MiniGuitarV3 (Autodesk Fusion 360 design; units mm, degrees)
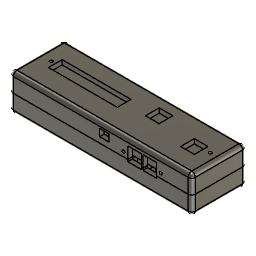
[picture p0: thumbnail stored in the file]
part number: 2026-04-03-11-49-24-486
part number: 2026-04-03-20-17-09-000
part number: 2026-04-03-20-17-09-014
part number: 2026-04-03-20-17-09-018
part number: 2026-04-03-20-17-09-022
part number: 2026-04-03-20-17-09-025
sketch "Sketch1" plane through (0, 0, 0) normal (0, 0, 1) x axis (1, 0, 0)
sketch "Sketch5" plane through (0, 0, 0) normal (0, 0, 1) x axis (1, 0, 0)
  line L1 (101.6, 0) -> (-152.4, 0)
  line L2 (101.6, -76.2) -> (101.6, 0)
  line L3 (-152.4, -76.2) -> (101.6, -76.2)
  line L4 (-152.4, 0) -> (-152.4, -76.2)
  horizontal L1
  perpendicular L1 L2
  perpendicular L2 L3
  perpendicular L1 L4
extrude "Extrude2" new body sketch "Sketch5" along normal blind 50.8
sketch "Sketch6" plane through (0, -76.2, 0) normal (0, -1, 0) x axis (1, 0, 0)
  line L1 (101.6, 0) -> (-152.4, 0)
  line L2 (101.6, 50.8) -> (101.6, 0)
  line L3 (-152.4, 50.8) -> (101.6, 50.8)
  line L4 (-152.4, 0) -> (-152.4, 50.8)
  line L5 (63.5, 25.4) -> (-127, 25.4)
  horizontal L5
split "Split2"
move "Move2"
shell "Shell3" innerThickness 6.35
shell "Shell4" innerThickness 6.35
sketch "Sketch7" plane through (0, 0, 73.66) normal (0, 0, 1) x axis (-1, 0, 0)
  line L1 (-101.6, 76.2) -> (152.4, 76.2)
  line L2 (-101.6, 0) -> (-101.6, 76.2)
  line L3 (152.4, 0) -> (-101.6, 0)
  line L4 (152.4, 76.2) -> (152.4, 0)
fillet "Fillet2" radius 5.08
fillet "Fillet3" radius 5.08
sketch "Sketch8" plane through (0, 0, 73.66) normal (0, 0, 1) x axis (-1, 0, 0)
sketch "Sketch9" plane through (0, 0, 73.66) normal (0, 0, 1) x axis (-1, 0, 0)
  line L1 (33.02, 25.4) -> (139.7, 25.4)
  line L2 (33.02, 15.9736) -> (33.02, 25.4)
  line L3 (-93.98, 15.9736) -> (33.02, 15.9736)
  line L4 (-93.98, 51.2796) -> (-93.98, 15.9736)
  line L5 (-53.34, 51.2796) -> (-93.98, 51.2796)
  line L6 (-53.34, 60.1632) -> (-53.34, 51.2796)
  line L7 (10.16, 60.1632) -> (-53.34, 60.1632)
  line L8 (10.16, 47.4632) -> (10.16, 60.1632)
  line L9 (139.7, 47.4632) -> (10.16, 47.4632)
  line L10 (139.7, 25.4) -> (139.7, 47.4632)
  point P5 (-93.98, 15.9736)
  point P6 (-93.98, 51.2796)
  point P9 (10.16, 60.1632)
  point P10 (10.16, 47.4632)
  horizontal L1
  perpendicular L1 L2
  perpendicular L2 L3
  perpendicular L3 L4
  perpendicular L4 L5
  perpendicular L5 L6
  perpendicular L6 L7
  perpendicular L7 L8
  perpendicular L8 L9
  perpendicular L1 L10
  dimension "d16" distance P5 P6 = 35.306
  dimension "d17" distance P9 P10 = 12.7
sketch "Sketch10" plane through (0, 0, 73.66) normal (0, 0, 1) x axis (-1, 0, 0)
  line L1 (134.2136, 35.56) -> (139.7, 35.56)
  point P2 (139.7, 35.56)
  point P3 (134.2136, 35.56)
  horizontal L1
  dimension "d18" distance P2 P3 = 5.4864
sketch "Sketch11" plane through (0, 0, 73.66) normal (0, 0, 1) x axis (-1, 0, 0)
  line L1 (139.8217, 36.3604) -> (139.8217, 25.3604)
  line L2 (134.3217, 36.3604) -> (139.8217, 36.3604)
  point P2 (139.8217, 25.3604)
  point P3 (139.8217, 36.3604)
  point P4 (134.3217, 36.3604)
  vertical L1
  perpendicular L1 L2
  dimension "d22" distance P2 P3 = 11
  dimension "d23" distance P3 P4 = 5.5
hole "Hole2" HoleDepth 13 HoleDiameter 4.1 TipAngle 118
sketch "Sketch12" plane through (0, 0, 73.66) normal (0, 0, 1) x axis (-1, 0, 0)
sketch "Sketch13" plane through (0, 0, 73.66) normal (0, 0, 1) x axis (-1, 0, 0)
  line L1 (-94, 36) -> (-94, 51)
  line L2 (-87.5, 36) -> (-94, 36)
  point P3 (-94, 36)
  point P4 (-87.5, 36)
  vertical L1
  perpendicular L1 L2
  dimension "d27" distance P3 P4 = 6.5
hole "Hole3" HoleDepth 13 HoleDiameter 4.1 TipAngle 118
sketch "Sketch14" plane through (0, 0, 73.66) normal (0, 0, 1) x axis (-1, 0, 0)
sketch "Sketch19" plane through (0, 0, 73.66) normal (0, 0, 1) x axis (-1, 0, 0)
  line L1 (51.5602, 45.9984) -> (42.0402, 45.9984)
  line L2 (51.5602, 26.9484) -> (51.5602, 45.9984)
  line L3 (32.5102, 26.9484) -> (51.5602, 26.9484)
  line L4 (32.5102, 45.9984) -> (32.5102, 26.9484)
  line L5 (42.0402, 45.9984) -> (32.5102, 45.9984)
  line L6 (51.7702, 46.0184) -> (61.2902, 46.0184)
  line L7 (51.7702, 27) -> (51.7702, 46.0184)
  line L8 (70.8202, 27) -> (51.7702, 27)
  line L9 (70.8202, 46.0184) -> (70.8202, 27)
  line L10 (61.2902, 46.0184) -> (70.8202, 46.0184)
  line L11 (71.0202, 46.0184) -> (80.5402, 46.0184)
  line L12 (71.0202, 27) -> (71.0202, 46.0184)
  line L13 (90.0702, 27) -> (71.0202, 27)
  line L14 (90.0702, 46.0184) -> (90.0702, 27)
  line L15 (80.5402, 46.0184) -> (90.0702, 46.0184)
  line L16 (90.2702, 46.0184) -> (99.7902, 46.0184)
  line L17 (90.2702, 26.9684) -> (90.2702, 46.0184)
  line L18 (109.3202, 26.9684) -> (90.2702, 26.9684)
  line L19 (109.4152, 46.0184) -> (109.3202, 26.9684)
  line L20 (99.7902, 46.0184) -> (109.4152, 46.0184)
  line L21 (109.5202, 46.0184) -> (119.0402, 46)
  line L22 (109.5202, 26.9684) -> (109.5202, 46.0184)
  line L23 (128.5702, 26.9684) -> (109.5202, 26.9684)
  line L24 (128.5702, 46.0184) -> (128.5702, 26.9684)
  line L25 (119.0402, 46) -> (128.5702, 46.0184)
  point P13 (71.0202, 46.0184)
  point P18 (90.2702, 46.0184)
  point P23 (109.5202, 46.0184)
  point P2 (42.0402, 45.9984)
  point P3 (51.5602, 45.9984)
  point P4 (51.5602, 26.9484)
  point P5 (32.5102, 26.9484)
  point P7 (61.2902, 46.0184)
  point P8 (51.7702, 46.0184)
  point P9 (51.7702, 27)
  point P10 (70.8202, 27)
  point P12 (80.5402, 46.0184)
  point P14 (71.0202, 27)
  point P15 (90.0702, 27)
  point P17 (99.7902, 46.0184)
  point P19 (90.2702, 26.9684)
  point P20 (109.3202, 26.9684)
  point P22 (119.0402, 46)
  point P24 (109.5202, 26.9684)
  point P25 (128.5702, 26.9684)
  perpendicular L1 L2
  perpendicular L2 L3
  perpendicular L3 L4
  perpendicular L2 L6
  perpendicular L6 L7
  perpendicular L7 L8
  perpendicular L6 L9
  coincident L10 P13
  perpendicular L9 L11
  perpendicular L10 L12
  perpendicular L9 L13
  perpendicular L13 L14
  coincident L15 P18
  perpendicular L14 L16
  perpendicular L13 L17
  perpendicular L17 L18
  coincident L20 P23
  perpendicular L18 L22
  perpendicular L22 L23
  perpendicular L18 L24
  dimension "d47" distance P2 P3 = 9.52
  dimension "d48" distance P3 P4 = 19.05
  dimension "d49" distance P4 P5 = 19.05
  dimension "d52" distance P7 P8 = 9.52
  dimension "d53" distance P9 P10 = 19.05
  dimension "d55" distance P12 P13 = 9.52
  dimension "d56" distance P14 P15 = 19.05
  dimension "d58" distance P17 P18 = 9.52
  dimension "d59" distance P18 P19 = 19.05
  dimension "d60" distance P19 P20 = 19.05
  dimension "d61" distance P22 P23 = 9.52
  dimension "d62" distance P24 P25 = 19.05
extrude "Extrude4" cut sketch "Sketch19" profile of L21 L22 L23 L24 L25 against normal blind 15
extrude "Extrude5" cut sketch "Sketch19" profile of L16 L17 L18 L19 L20 against normal blind 8
extrude "Extrude6" cut sketch "Sketch19" profile of L11 L12 L13 L14 L15 against normal blind 12
extrude "Extrude7" cut sketch "Sketch19" profile of L6 L7 L8 L9 L10 against normal blind 10
extrude "Extrude8" cut sketch "Sketch19" profile of L1 L2 L3 L4 L5 against normal blind 7
sketch "Sketch20" plane through (0, 0, 73.66) normal (0, 0, 1) x axis (-1, 0, 0)
  line L1 (128.5789, 46) -> (128.5789, 26.9688)
  line L2 (32.5156, 46) -> (128.5789, 46)
  line L3 (32.5046, 26.9365) -> (32.5156, 46)
  line L4 (128.5789, 26.8811) -> (32.5046, 26.9365)
  line L5 (128.5789, 27.2773) -> (128.5789, 26.8811)
  point P7 (128.5789, 27.2773)
  vertical L1
  perpendicular L1 L2
  perpendicular L3 L4
  coincident L1 P7
  parallel L1 L5
extrude "Extrude9" cut sketch "Sketch20" against normal blind 8
sketch "Sketch21" plane through (0, 0, 73.66) normal (0, 0, 1) x axis (-1, 0, 0)
sketch "Sketch22" plane through (0, 0, 73.66) normal (0, 0, 1) x axis (-1, 0, 0)
  line L1 (2.52, 17.48) -> (2.52, 27)
  line L2 (-16.53, 17.48) -> (2.52, 17.48)
  line L3 (-16.53, 36.53) -> (-16.53, 17.48)
  line L4 (2.52, 36.53) -> (-16.53, 36.53)
  line L5 (2.52, 27) -> (2.52, 36.53)
  point P2 (2.52, 27)
  point P3 (2.52, 17.48)
  point P4 (-16.53, 17.48)
  point P5 (-16.53, 36.53)
  perpendicular L1 L2
  perpendicular L2 L3
  perpendicular L3 L4
  dimension "d83" distance P2 P3 = 9.52
  dimension "d84" distance P3 P4 = 19.05
  dimension "d85" distance P4 P5 = 19.05
extrude "Extrude10" cut sketch "Sketch22" against normal blind 11
sketch "Sketch23" plane through (0, 0, 73.66) normal (0, 0, 1) x axis (-1, 0, 0)
  line L1 (-59.1985, 49.1388) -> (-59.1985, 39.6188)
  line L2 (-78.2485, 49.1388) -> (-59.1985, 49.1388)
  line L3 (-78.2485, 30.0888) -> (-78.2485, 49.1388)
  line L4 (-59.1985, 30.0888) -> (-78.2485, 30.0888)
  line L5 (-59.1985, 39.6188) -> (-59.1985, 30.0888)
  point P2 (-59.1985, 39.6188)
  point P3 (-59.1985, 49.1388)
  point P4 (-78.2485, 49.1388)
  point P5 (-78.2485, 30.0888)
  point P6 (-59.1985, 30.0888)
  perpendicular L1 L2
  perpendicular L3 L4
  dimension "d90" distance P2 P3 = 9.52
  dimension "d91" distance P3 P4 = 19.05
  dimension "d92" distance P4 P5 = 19.05
  dimension "d93" distance P5 P6 = 19.05
extrude "Extrude11" cut sketch "Sketch23" against normal blind 12
sketch "Sketch24" plane through (0, -76.2, 0) normal (0, -1, 0) x axis (1, 0, 0)
  line L1 (-147.32, 48.26) -> (-147.32, 68.58)
  line L2 (96.52, 48.26) -> (-147.32, 48.26)
  line L3 (96.52, 68.58) -> (96.52, 48.26)
  line L4 (-147.32, 68.58) -> (96.52, 68.58)
move "Move3"
fillet "Fillet4" radius 5
move "Move4"
move "Move5"
sketch "Sketch25" plane through (0, -76.2, 0) normal (0, -1, 0) x axis (1, 0, 0)
sketch "Sketch26" plane through (0, -76.2, 0) normal (0, -1, 0) x axis (1, 0, 0)
sketch "Sketch27" plane through (0, -76.2, 0) normal (0, -1, 0) x axis (1, 0, 0)
sketch "Sketch28" plane through (0, -76.2, 0) normal (0, -1, 0) x axis (1, 0, 0)
  line L1 (1, 44) -> (1, 65)
  vertical L1
sketch "Sketch29" plane through (0, -76.2, 0) normal (0, -1, 0) x axis (1, 0, 0)
  line L1 (65, 54.5) -> (65, 65)
  line L2 (58.5, 54.5) -> (65, 54.5)
  point P2 (65, 65)
  point P3 (65, 54.5)
  point P4 (58.5, 54.5)
  vertical L1
  perpendicular L1 L2
  dimension "d99" distance P2 P3 = 10.5
  dimension "d100" distance P3 P4 = 6.5
hole "Hole4" HoleDepth 13 HoleDiameter 4.1 TipAngle 118
sketch "Sketch30" plane through (0, -76.2, 0) normal (0, -1, 0) x axis (1, 0, 0)
  line L1 (1, 54.5) -> (1, 65)
  line L2 (6.5, 54.5) -> (1, 54.5)
  point P2 (1, 65)
  point P3 (1, 54.5)
  point P4 (6.5, 54.5)
  vertical L1
  perpendicular L1 L2
  dimension "d104" distance P2 P3 = 10.5
  dimension "d105" distance P3 P4 = 5.5
hole "Hole5" HoleDepth 13 HoleDiameter 4.1 TipAngle 118
sketch "Sketch31" plane through (0, -76.2, 0) normal (0, -1, 0) x axis (1, 0, 0)
sketch "Sketch32" plane through (0, -76.2, 0) normal (0, -1, 0) x axis (1, 0, 0)
  line L1 (33.48, 45.48) -> (43, 45.48)
  line L2 (33.48, 64.53) -> (33.48, 45.48)
  line L3 (52.53, 64.53) -> (33.48, 64.53)
  line L4 (52.53, 45.48) -> (52.53, 64.53)
  line L5 (43, 45.48) -> (52.53, 45.48)
  point P2 (43, 45.48)
  point P3 (33.48, 45.48)
  point P4 (33.48, 64.53)
  point P5 (52.53, 64.53)
  perpendicular L1 L2
  perpendicular L3 L4
  dimension "d111" distance P2 P3 = 9.52
  dimension "d112" distance P3 P4 = 19.05
  dimension "d113" distance P4 P5 = 19.05
sketch "Sketch33" plane through (0, -76.2, 0) normal (0, -1, 0) x axis (1, 0, 0)
  line L1 (12.48, 64.52) -> (22, 64.52)
  line L2 (12.48, 45.47) -> (12.48, 64.52)
  line L3 (31.53, 45.47) -> (12.48, 45.47)
  line L4 (31.53, 64.52) -> (31.53, 45.47)
  line L5 (22, 64.52) -> (31.53, 64.52)
  point P2 (22, 64.52)
  point P3 (12.48, 64.52)
  point P4 (12.48, 45.47)
  point P5 (31.53, 45.47)
  perpendicular L2 L3
  dimension "d116" distance P2 P3 = 9.52
  dimension "d117" distance P3 P4 = 19.05
  dimension "d118" distance P4 P5 = 19.05
extrude "Extrude12" cut sketch "Sketch33" against normal blind 17
extrude "Extrude13" cut sketch "Sketch32" against normal blind 24
sketch "Sketch34" plane through (0, -76.2, 0) normal (0, -1, 0) x axis (1, 0, 0)
  line L1 (-14, 66) -> (-27, 66)
  line L2 (-14, 56) -> (-14, 66)
  line L3 (-27, 56) -> (-14, 56)
  line L4 (-27, 66) -> (-27, 56)
  horizontal L1
  perpendicular L1 L2
  perpendicular L2 L3
  perpendicular L1 L4
extrude "Extrude14" cut sketch "Sketch34" against normal blind 11
move "Move6"
move "Move7"
extrude "Extrude15" new body sketch "Sketch9" along normal blind 3
move "Move8"
move "Move9"
sketch "Sketch35" plane through (0, -76.2, 0) normal (0, -1, 0) x axis (1, 0, 0)
  line L1 (-14, 46) -> (-14, 56)
  line L2 (-27, 46) -> (-14, 46)
  line L3 (-27, 56) -> (-27, 46)
  line L4 (-14, 56) -> (-27, 56)
  line L5 (33.48, 54.53) -> (33.48, 38.26)
  line L6 (52.53, 54.53) -> (33.48, 54.53)
  line L7 (52.53, 38.26) -> (52.53, 54.53)
  line L8 (96.52, 38.26) -> (52.53, 38.26)
  line L9 (96.52, 58.58) -> (96.52, 38.26)
  line L10 (-147.32, 58.58) -> (96.52, 58.58)
  line L11 (-147.32, 38.26) -> (-147.32, 58.58)
  line L12 (12.48, 38.26) -> (-147.32, 38.26)
  line L13 (12.48, 54.52) -> (12.48, 38.26)
  line L14 (31.53, 54.52) -> (12.48, 54.52)
  line L15 (31.53, 38.26) -> (31.53, 54.52)
  line L16 (33.48, 38.26) -> (31.53, 38.26)
  line L17 (1, 55) -> (1, 44.5)
  line L18 (63, 55) -> (1, 55)
  line L19 (63, 34) -> (63, 55)
  line L20 (1, 34) -> (63, 34)
  line L21 (1, 44.5) -> (1, 34)
  circle C1 centre (6.5, 44.5) radius 2.05
  circle C2 centre (58.5, 44.5) radius 2.05
  perpendicular L12 L17
  perpendicular L17 L18
  perpendicular L18 L19
  perpendicular L19 L20
move "Move10"
move "Move11"
extrude "Extrude20" new body sketch "Sketch35" profile of C1 C2 L5 L6 L7 L8 L12 L13 L14 L15 L16 L17 L18 L19 L20 L21 along normal blind 2
move "Move12"
move "Move13"
move "Move14"
move "Move17"
move "Move18"
move "Move19"
move "Move33"
move "Move34"
move "Move35"
sketch "Sketch38" plane through (0, 0, 19.176) normal (0, 0, 1) x axis (-1, 0, 0)
  line L1 (-95.25, 199.3753) -> (146.05, 199.3753)
  line L2 (-95.25, 135.8753) -> (-95.25, 199.3753)
  line L3 (146.05, 135.8753) -> (-95.25, 135.8753)
  line L4 (146.05, 199.3753) -> (146.05, 135.8753)
  line L5 (140.1158, 199.3753) -> (140.1158, 135.8753)
  line L6 (130.7236, 135.8753) -> (130.7236, 199.3753)
  line L7 (130.7236, 135.8753) -> (140.1158, 135.8753)
  line L8 (140.1158, 199.3753) -> (130.7236, 199.3753)
  line L9 (105, 135.8753) -> (115.2489, 135.8753)
  line L10 (115, 199.3753) -> (105, 199.3753)
  line L11 (115, 199.3753) -> (115.2489, 135.8753)
  line L12 (105, 135.8753) -> (105, 199.3753)
  line L13 (80.0335, 135.8753) -> (90.0335, 135.8753)
  line L14 (80.0335, 199.3753) -> (80.0335, 135.8753)
  line L15 (90.0335, 135.8753) -> (90.2987, 199.3753)
  line L16 (80.0335, 199.3753) -> (90.2987, 199.3753)
  line L17 (55, 135.8753) -> (65.0397, 135.8753)
  line L18 (55, 135.8753) -> (55, 199.3753)
  line L19 (65.0397, 199.3753) -> (65.0397, 135.8753)
  line L20 (65.0397, 199.3753) -> (55, 199.3753)
  line L21 (30, 135.8753) -> (40.2799, 135.8753)
  line L22 (30, 135.8753) -> (30, 199.3753)
  line L23 (40.2799, 199.3753) -> (40.2799, 135.8753)
  line L24 (40.2799, 199.3753) -> (30, 199.3753)
  line L25 (5, 135.8753) -> (15.021, 135.8753)
  line L26 (5, 135.8753) -> (5, 199.3753)
  line L27 (15.021, 199.3753) -> (15.021, 135.8753)
  line L28 (15.021, 199.3753) -> (5, 199.3753)
  line L29 (-20, 135.8753) -> (-10.0383, 135.8753)
  line L30 (-10.0383, 190) -> (-20, 190)
  line L31 (-10.0383, 135.8753) -> (-10.0383, 190)
  line L32 (-20, 190) -> (-20, 135.8753)
  line L33 (-45, 190) -> (-35, 190)
  line L34 (-45, 135.8753) -> (-45, 190)
  line L35 (-35, 190) -> (-35.0976, 135.8753)
  line L36 (-70.041, 190.0181) -> (-60, 190)
  line L37 (-70.041, 135.8753) -> (-70.041, 190.0181)
  line L38 (-60, 190) -> (-59.9573, 135.8753)
  line L39 (-70.041, 135.8753) -> (-59.9573, 135.8753)
  line L40 (-85.1164, 199.3753) -> (-85.1164, 135.8753)
  line L41 (-95.25, 136) -> (-95.25, 199.3753)
  line L42 (-95.25, 199.3753) -> (-85.1164, 199.3753)
  line L43 (-95.25, 136) -> (-85.1164, 135.8753)
  line L44 (-95.25, 199.3753) -> (-95.25, 136)
  point P6 (140.1158, 135.8753)
  point P7 (140.1158, 199.3753)
  point P8 (130.7236, 199.3753)
  point P9 (130.7236, 135.8753)
  point P10 (115.2489, 135.8753)
  point P11 (105, 135.8753)
  point P12 (105, 199.3753)
  point P13 (115, 199.3753)
  point P14 (90.0335, 135.8753)
  point P15 (80.0335, 135.8753)
  point P16 (80.0335, 199.3753)
  point P17 (90.2987, 199.3753)
  point P18 (65.0397, 135.8753)
  point P19 (55, 135.8753)
  point P20 (55, 199.3753)
  point P21 (65.0397, 199.3753)
  point P22 (40.2799, 135.8753)
  point P23 (30, 135.8753)
  point P24 (30, 199.3753)
  point P25 (40.2799, 199.3753)
  point P26 (15.021, 135.8753)
  point P27 (5, 135.8753)
  point P28 (5, 199.3753)
  point P29 (15.021, 199.3753)
  point P30 (-10.0383, 135.8753)
  point P31 (-20, 135.8753)
  point P36 (-45, 135.8753)
  point P37 (-35.0976, 135.8753)
  point P40 (-70.041, 135.8753)
  point P41 (-59.9573, 135.8753)
  point P42 (-85.1164, 135.8753)
  point P43 (-85.1164, 199.3753)
  point P3 (-95.25, 199.3753)
  point P44 (-95.25, 199.3753)
  point P45 (-95.25, 136)
  coincident L3 P6
  coincident L1 P7
  perpendicular L1 L5
  coincident L1 P8
  coincident L3 P9
  perpendicular L3 L6
  coincident L3 P10
  coincident L3 P11
  coincident L1 P12
  coincident L1 P13
  perpendicular L9 L12
  coincident L3 P14
  coincident L3 P15
  coincident L1 P16
  perpendicular L1 L14
  coincident L1 P17
  coincident L3 P18
  coincident L3 P19
  coincident L1 P20
  perpendicular L17 L18
  coincident L1 P21
  perpendicular L1 L19
  coincident L3 P22
  coincident L3 P23
  coincident L1 P24
  perpendicular L1 L22
  coincident L1 P25
  perpendicular L1 L23
  coincident L3 P26
  coincident L3 P27
  coincident L1 P28
  perpendicular L25 L26
  coincident L1 P29
  perpendicular L1 L27
  coincident L3 P30
  coincident L3 P31
  parallel L29 L30
  perpendicular L29 L31
  perpendicular L30 L32
  perpendicular L32 L33
  coincident L3 P36
  perpendicular L3 L34
  coincident L3 P37
  perpendicular L35 L36
  coincident L3 P40
  perpendicular L3 L37
  coincident L3 P41
  coincident L3 P42
  coincident L1 P43
  perpendicular L1 L40
  coincident P3 P44
  coincident L2 P45
  dimension "d139" distance P14 P15 = 10
extrude "Extrude32" add sketch "Sketch38" profile of L1 L3 L5 L6 L7 L8 along normal blind 31
shell "Shell9" innerThickness 2
extrude "Extrude33" add sketch "Sketch38" profile of L1 L3 L9 L10 L11 L12 along normal blind 31
shell "Shell10" innerThickness 2
extrude "Extrude34" add sketch "Sketch38" profile of L1 L3 L13 L14 L15 L16 along normal blind 31
shell "Shell11" innerThickness 2
extrude "Extrude35" add sketch "Sketch38" profile of L1 L3 L17 L18 L19 L20 along normal blind 31
shell "Shell12" innerThickness 2
extrude "Extrude36" add sketch "Sketch38" profile of L1 L3 L21 L22 L23 L24 along normal blind 31
shell "Shell13" innerThickness 2
extrude "Extrude37" add sketch "Sketch38" profile of L1 L3 L25 L26 L27 L28 along normal blind 31
shell "Shell14" innerThickness 2
extrude "Extrude38" add sketch "Sketch38" profile of L3 L29 L30 L31 L32 along normal blind 31
shell "Shell15" innerThickness 2
extrude "Extrude39" add sketch "Sketch38" profile of L3 L33 L34 L35 along normal blind 31
shell "Shell16" innerThickness 2
extrude "Extrude40" add sketch "Sketch38" profile of L3 L36 L37 L38 L39 along normal blind 31
shell "Shell17" innerThickness 2
extrude "Extrude41" new body sketch "Sketch38" profile of L1 L2 L40 L41 L42 L43 L44 along normal blind 31
shell "Shell18" innerThickness 2
move "Move30"
move "Move31"
move "Move32"
hole "Hole8" HoleDepth 62 HoleDiameter 4.1 TipAngle 118
hole "Hole9" HoleDepth 62 HoleDiameter 4.1 TipAngle 118
component_from_bodies "Body->Comp1"
component_from_bodies "Body->Comp2"
component_from_bodies "Body->Comp3"
component_from_bodies "Body->Comp4"
component_from_bodies "Body->Comp5"
sketch "Sketch39" plane through (0, 0, 63.66) normal (0, 0, 1) x axis (-1, 0, 0)
  line L1 (-59.1985, 178.6388) -> (-78.2485, 178.6388)
  line L2 (-59.1985, 159.5888) -> (-59.1985, 178.6388)
  line L3 (-78.2485, 159.5888) -> (-59.1985, 159.5888)
  line L4 (-78.2485, 178.6388) -> (-78.2485, 159.5888)
  line L5 (-16.53, 166.03) -> (-16.53, 146.98)
  line L6 (2.52, 166.03) -> (-16.53, 166.03)
  line L7 (2.52, 146.98) -> (2.52, 166.03)
  line L8 (-16.53, 146.98) -> (2.52, 146.98)
  line L9 (-96.52, 200.62) -> (147.32, 200.62)
  line L10 (-96.52, 134.58) -> (-96.52, 200.62)
  line L11 (147.32, 134.58) -> (-96.52, 134.58)
  line L12 (147.32, 200.62) -> (147.32, 134.58)
  line L13 (90.2702, 175.5) -> (90.0702, 175.5)
  line L14 (90.2702, 175.5184) -> (90.2702, 175.5)
  line L15 (109.4152, 175.5184) -> (90.2702, 175.5184)
  line L16 (109.4151, 175.5) -> (109.4152, 175.5184)
  line L17 (109.5202, 175.5) -> (109.4151, 175.5)
  line L18 (109.5202, 175.5184) -> (109.5202, 175.5)
  line L19 (119.0402, 175.5) -> (109.5202, 175.5184)
  line L20 (128.5702, 175.5184) -> (119.0402, 175.5)
  line L21 (128.5702, 175.5) -> (128.5702, 175.5184)
  line L22 (128.5789, 175.5) -> (128.5702, 175.5)
  line L23 (128.5789, 156.3811) -> (128.5789, 175.5)
  line L24 (32.5046, 156.4365) -> (128.5789, 156.3811)
  line L25 (32.5102, 165.9915) -> (32.5046, 156.4365)
  line L26 (32.5102, 175.4984) -> (32.5102, 165.9915)
  line L27 (32.5156, 175.4984) -> (32.5102, 175.4984)
  line L28 (32.5156, 175.5) -> (32.5156, 175.4984)
  line L29 (51.7702, 175.5) -> (32.5156, 175.5)
  line L30 (51.7702, 175.5184) -> (51.7702, 175.5)
  line L31 (70.8202, 175.5184) -> (51.7702, 175.5184)
  line L32 (70.8202, 175.5) -> (70.8202, 175.5184)
  line L33 (71.0202, 175.5) -> (70.8202, 175.5)
  line L34 (71.0202, 175.5184) -> (71.0202, 175.5)
  line L35 (90.0702, 175.5184) -> (71.0202, 175.5184)
  line L36 (90.0702, 175.5) -> (90.0702, 175.5184)
  line L37 (25.4, 152.4) -> (25.4, 190.5)
  circle C1 centre (134.3217, 165.8604) radius 2.05
  circle C2 centre (-87.5, 165.5) radius 2.05
  vertical L37
move "Move1"
move "Move1"
move "Move1"
move "Move2"
split "Split1"
sketch "Sketch40" plane through (0, -205.7253, 0) normal (0, -1, 0) x axis (1, 0, 0)
  line L1 (52.53, 35.506) -> (52.53, 38.226)
  line L2 (33.48, 35.506) -> (52.53, 35.506)
  line L3 (33.48, 38.226) -> (33.48, 35.506)
  line L4 (31.53, 38.226) -> (33.48, 38.226)
  line L5 (31.53, 35.496) -> (31.53, 38.226)
  line L6 (12.48, 35.496) -> (31.53, 35.496)
  line L7 (12.48, 38.226) -> (12.48, 35.496)
  line L8 (-147.4, 38.226) -> (12.48, 38.226)
  line L9 (-147.4, 17.826) -> (-147.4, 38.226)
  line L10 (96.6, 17.826) -> (-147.4, 17.826)
  line L11 (96.6, 38.226) -> (96.6, 17.826)
  line L12 (52.53, 38.226) -> (96.6, 38.226)
  line L13 (-25.4, 19.05) -> (-25.4, 35.56)
  perpendicular L8 L13
split "Split1"
move "Move3"
move "Move4"
extrude "Extrude22" add sketch "Sketch38" profile of L3 L29 L30 L31 L32 along normal blind 31
extrude "Extrude23" add sketch "Sketch38" profile of L1 L3 L5 L6 L7 L8 along normal blind 31
extrude "Extrude24" add sketch "Sketch38" profile of L1 L3 L9 L10 L11 L12 along normal blind 31
extrude "Extrude25" add sketch "Sketch38" profile of L1 L3 L13 L14 L15 L16 along normal blind 31
extrude "Extrude26" add sketch "Sketch38" profile of L1 L3 L17 L18 L19 L20 along normal blind 31
extrude "Extrude27" add sketch "Sketch38" profile of L1 L3 L21 L22 L23 L24 along normal blind 31
extrude "Extrude28" add sketch "Sketch38" profile of L1 L3 L25 L26 L27 L28 along normal blind 31
extrude "Extrude29" add sketch "Sketch38" profile of L3 L33 L34 L35 along normal blind 31
extrude "Extrude30" add sketch "Sketch38" profile of L3 L36 L37 L38 L39 along normal blind 31
extrude "Extrude31" new body sketch "Sketch38" profile of L1 L2 L40 L41 L42 L43 L44 along normal blind 31
shell "Shell7" innerThickness 2
shell "Shell8" innerThickness 2
move "Move29"
move "Move20"
move "Move21"
move_face "MoveFace2"
move "Move22"
move "Move23"
move "Move24"
move "Move25"
move "Move26"
hole "Hole6" HoleDepth 62 HoleDiameter 4.1 TipAngle 118
hole "Hole7" HoleDepth 62 HoleDiameter 4.1 TipAngle 118
move "Move27"
move "Move28"
shell "Shell5" innerThickness 2
shell "Shell6" innerThickness 2
sketch "Sketch36" plane through (0, 0, 9.15) normal (0, 0, 1) x axis (-1, 0, 0)
  line L1 (-95.25, 194.85) -> (146.05, 194.85)
  line L2 (-95.25, 131.35) -> (-95.25, 194.85)
  line L3 (146.05, 131.35) -> (-95.25, 131.35)
  line L4 (146.05, 194.85) -> (146.05, 131.35)
  line L5 (135.643, 131.35) -> (-95.25, 189.9038)
  line L6 (146.05, 139.7193) -> (-79.9064, 194.85)
  line L7 (-95.25, 194.85) -> (-95.25, 189.9038)
  line L8 (-95.25, 194.85) -> (-79.9064, 194.85)
  line L9 (146.05, 131.35) -> (146.05, 139.7193)
  line L10 (146.05, 131.35) -> (135.643, 131.35)
  point P6 (-95.25, 189.9038)
  point P7 (135.643, 131.35)
  point P8 (-79.9064, 194.85)
  point P9 (146.05, 139.7193)
  point P3 (-95.25, 194.85)
  point P10 (-95.25, 194.85)
  point P5 (146.05, 131.35)
  point P11 (146.05, 131.35)
  coincident L2 P6
  coincident L3 P7
  coincident L1 P8
  coincident L4 P9
  coincident P3 P10
  coincident P5 P11
extrude "Extrude21" add sketch "Sketch36" along normal blind 19
sketch "Sketch37" plane through (0, 0, 28.15) normal (0, 0, 1) x axis (-1, 0, 0)
  line L1 (135.643, 131.35) -> (-95.25, 189.9038)
  line L2 (146.05, 131.35) -> (135.643, 131.35)
  line L3 (146.05, 139.7193) -> (146.05, 131.35)
  line L4 (-79.9064, 194.85) -> (146.05, 139.7193)
  line L5 (-95.25, 194.85) -> (-79.9064, 194.85)
  line L6 (-95.25, 189.9038) -> (-95.25, 194.85)
move "Move15"
move "Move16"
extrude "Extrude18" new body sketch "Sketch35" profile of L5 L6 L7 L8 L12 L13 L14 L15 L16 L19 L20 L21 along normal blind 2
extrude "Extrude19" add sketch "Sketch35" profile of C1 C2 L5 L6 L7 L8 L12 L13 L14 L15 L16 L17 L18 L19 L21 along normal blind 2
move_face "MoveFace1"
extrude "Extrude16" add sketch "Sketch35" profile of C1 C2 L5 L6 L7 L8 L12 L13 L14 L15 L16 L17 L18 L19 L21 along normal blind 2
extrude "Extrude17" add sketch "Sketch35" profile of L5 L6 L7 L8 L12 L13 L14 L15 L16 L19 L20 L21 along normal blind 2
sketch "Sketch15" plane through (0, 0, 73.66) normal (0, 0, 1) x axis (-1, 0, 0)
sketch "Sketch16" plane through (0, 0, 0) normal (0, 1, 0) x axis (1, 0, 0)
sketch "Sketch17" plane through (0, 0, 73.66) normal (0, 0, 1) x axis (-1, 0, 0)
sketch "Sketch18" plane through (0, 0, 73.66) normal (0, 0, 1) x axis (-1, 0, 0)
  line L1 (109.5, 46.02) -> (109.5, 36.5)
  line L2 (128.55, 46.02) -> (109.5, 46.02)
  line L3 (128.55, 26.97) -> (128.55, 46.02)
  line L4 (109.5, 26.97) -> (128.55, 26.97)
  line L5 (109.5, 36.5) -> (109.5, 26.97)
  point P2 (109.5, 36.5)
  point P3 (109.5, 46.02)
  point P4 (128.55, 46.02)
  point P5 (128.55, 26.97)
  point P6 (109.5, 26.97)
  vertical L1
  perpendicular L1 L2
  perpendicular L2 L3
  perpendicular L3 L4
  dimension "d35" distance P2 P3 = 9.52
  dimension "d36" distance P3 P4 = 19.05
  dimension "d37" distance P4 P5 = 19.05
  dimension "d38" distance P5 P6 = 19.05
extrude "Extrude3" cut sketch "Sketch18" against normal blind 19
hole "Hole1" HoleDepth 3.2 HoleDiameter 3.2 TipAngle 118
sketch "Sketch2" plane through (0, 0, 0) normal (0, 0, 1) x axis (1, 0, 0)
  line L1 (88.9, 12.7) -> (-152.4, 12.7)
  line L2 (88.9, -50.8) -> (88.9, 12.7)
  line L3 (-152.4, -50.8) -> (88.9, -50.8)
  line L4 (-152.4, 12.7) -> (-152.4, -50.8)
  horizontal L1
  perpendicular L1 L2
  perpendicular L2 L3
  perpendicular L1 L4
extrude "Extrude1" new body sketch "Sketch2" along normal blind 50.8
sketch "Sketch3" plane through (0, -50.8, 0) normal (0, -1, 0) x axis (1, 0, 0)
  line L1 (88.9, 0) -> (-152.4, 0)
  line L2 (88.9, 50.8) -> (88.9, 0)
  line L3 (-152.4, 50.8) -> (88.9, 50.8)
  line L4 (-152.4, 0) -> (-152.4, 50.8)
  line L5 (38.1, 25.4) -> (-114.3, 25.4)
  horizontal L5
split "Split1"
move "Move1"
shell "Shell1" innerThickness 6.35
shell "Shell2" innerThickness 6.35
fillet "Fillet1" radius 7.62
sketch "Sketch4" plane through (0, 0, 68.58) normal (0, 0, 1) x axis (-1, 0, 0)
  line L1 (-81.28, -5.08) -> (-81.28, 43.18)
  line L2 (144.78, -5.08) -> (-81.28, -5.08)
  line L3 (144.78, 43.18) -> (144.78, -5.08)
  line L4 (-81.28, 43.18) -> (144.78, 43.18)
  circle C1 centre (141, 19) radius 1.75
  dimension "d7" diameter C1 = 3.5
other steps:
create_component "CreateComponent1"
base_feature "Base Feature1"
reparent_decal "ReparentDecal1"
remove_body "RemoveBody1"
create_component "CreateComponent2"
base_feature "Base Feature1"
reparent_decal "ReparentDecal2"
remove_body "RemoveBody2"
create_component "CreateComponent3"
base_feature "Base Feature1"
reparent_decal "ReparentDecal3"
remove_body "RemoveBody3"
create_component "CreateComponent4"
base_feature "Base Feature1"
reparent_decal "ReparentDecal4"
remove_body "RemoveBody4"
create_component "CreateComponent5"
base_feature "Base Feature1"
reparent_decal "ReparentDecal5"
remove_body "RemoveBody5"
